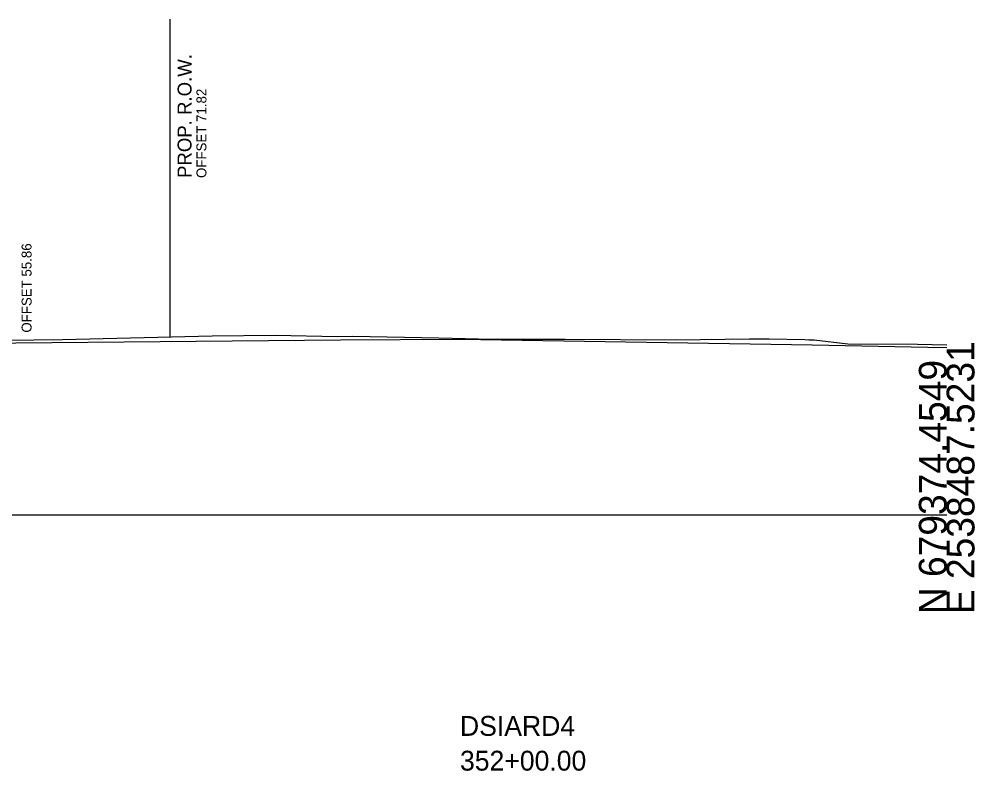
# Model space of a CAD drawing. Extents: x -26 to 1603, y -30 to 14537.
# Drawn here: x 206.6 to 302.8, y 2974.2 to 3049.9 of the extents above; entities that cross this region are included whole.
import ezdxf

# ---------------------------------------------------------------- set-up
doc = ezdxf.new("R2010")
doc.units = 0
for name, color, linetype in [('DESIGN - ROW - Right-of-Way and Easement Labels', 7, 'Continuous'), ('DESIGN - ROW - Right-of-Way Linework', 7, 'Continuous'), ('DESIGN - SHEET - Light Grid', 7, 'Continuous'), ('DESIGN - TYPICAL - Slope Tie Text', 7, 'Continuous'), ('DESIGN - TYPICAL - Warning Text', 7, 'Continuous'), ('SURVEY - GROUND - Top of Ground', 7, 'Continuous')]:
    doc.layers.add(name, color=color, linetype=linetype)

msp = doc.modelspace()

# ---------------------------------------------------------------- linework, layer by layer
at = {"layer": 'DESIGN - ROW - Right-of-Way Linework'}
msp.add_line((221.82, 3017.932), (221.82, 3049.932), dxfattribs=at)
at = {"layer": 'DESIGN - SHEET - Light Grid'}
msp.add_line((150, 3000), (300, 3000), dxfattribs=at)
at = {"layer": 'SURVEY - GROUND - Top of Ground'}
for points in [[(0, 3001.298), (24.443, 3001.973), (31.751, 3002.006), (38.564, 3002.419), (55.628, 3001.91), (74.857, 3001.606), (91.41, 3006.361), (113.435, 3010.386), (121.539, 3014.447), (128.664, 3014.618), (142.408, 3015.262), (150, 3015.505), (165.545, 3016.004), (189.775, 3017.182), (206.276, 3017.316), (238.965, 3017.625), (251.025, 3017.71), (286.472, 3017.121), (298.09, 3016.889), (300, 3016.85)], [(202.263, 3017.57), (210.965, 3017.661), (226.061, 3018.038), (232.389, 3018.1), (238.66, 3017.963), (240.22, 3018.006), (248.872, 3017.819), (254.208, 3017.698), (261.595, 3017.692), (272.76, 3017.63), (280.157, 3017.719), (280.782, 3017.725), (282.132, 3017.726), (285.722, 3017.665), (286.136, 3017.648), (286.662, 3017.636), (290.043, 3017.244), (297.054, 3017.193), (300, 3017.132)]]:
    msp.add_lwpolyline(points, dxfattribs=at)

# ---------------------------------------------------------------- texts
at = {"layer": 'DESIGN - ROW - Right-of-Way and Easement Labels'}
for s, height, p in [('PROP. R.O.W.', 1.4, (223.97, 3033.932)), ('OFFSET 71.82', 1, (225.47, 3033.932))]:
    msp.add_text(s, height=height, rotation=90, dxfattribs=at).set_placement(p)
at = {"layer": 'DESIGN - SHEET - Light Grid'}
for s, p in [('E 2538487.5231', (302.8, 2990)), ('N 679374.4549', (300, 2990))]:
    msp.add_text(s, height=2.8, rotation=90, dxfattribs=at).set_placement(p)
at = {"layer": 'DESIGN - TYPICAL - Slope Tie Text'}
msp.add_text('OFFSET 55.86', height=1, rotation=90, dxfattribs=at).set_placement((207.864, 3018.358))
at = {"layer": 'DESIGN - TYPICAL - Warning Text'}
for s, p in [('DSIARD4', (251, 2977.75)), ('352+00.00', (251, 2974.25))]:
    msp.add_text(s, height=2, dxfattribs=at).set_placement(p)

doc.saveas('drawing.dxf')
